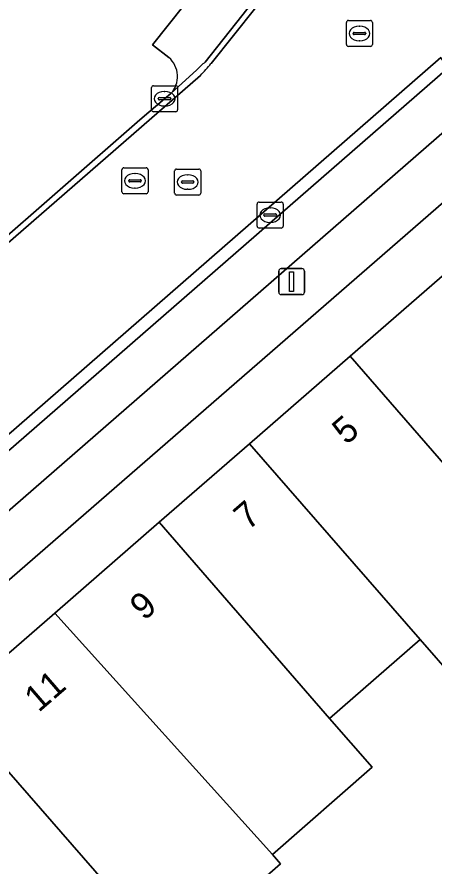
# Model space of a CAD drawing. Extents: x 161881 to 162523, y 381678 to 382381.
# Drawn here: x 162073.2 to 162089.24, y 382104.65 to 382137.32 of the extents above; entities that cross this region are included whole.
import ezdxf

# ---------------------------------------------------------------- set-up
doc = ezdxf.new("R2010")
doc.units = 0
for name, color, linetype in [('IMGEO_Erf', 7, 'Continuous'), ('IMGEO_Kolk', 7, 'Continuous'), ('IMGEO_Lichtmast', 7, 'Continuous'), ('IMGEO_Pand', 7, 'Continuous'), ('IMGEO_Pand_nummerreeks', 7, 'Continuous'), ('IMGEO_Parkeervlak_open', 7, 'Continuous'), ('IMGEO_Rijbaan_lokaal_open', 7, 'Continuous'), ('IMGEO_Rioolput', 7, 'Continuous'), ('IMGEO_Voetpad_open', 7, 'Continuous')]:
    doc.layers.add(name, color=color, linetype=linetype)

msp = doc.modelspace()

# ---------------------------------------------------------------- linework, layer by layer
at = {"layer": 'IMGEO_Erf'}
for points in [[(162094.812, 382134.731), (162045.016, 382091.412), (162046.474, 382089.736), (162054.365, 382081.454)], [(162054.137, 382083.272), (162047.556, 382090.818), (162051.36, 382094.127), (162055.4, 382097.641), (162059.405, 382101.124), (162062.911, 382104.174), (162066.755, 382107.518), (162070.6, 382110.862), (162074.647, 382114.382), (162078.667, 382117.878), (162082.144, 382120.902), (162086.012, 382124.267), (162090.338, 382128.029)], [(162090.02, 382111.857), (162088.706, 382113.366), (162085.22, 382110.331), (162086.856, 382108.447), (162083.028, 382105.097), (162083.336, 382104.728), (162079.152, 382101.078), (162078.812, 382101.467), (162074.973, 382098.113), (162071.133, 382094.758), (162070.479, 382095.507), (162066.981, 382092.451), (162067.968, 382091.321), (162063.941, 382087.819), (162059.914, 382084.317)]]:
    msp.add_lwpolyline(points, dxfattribs=at)
at = {"layer": 'IMGEO_Kolk'}
for p, q in [((162078.373, 382133.752), (162078.373, 382134.604)), ((162078.448, 382134.678), (162079.3, 382134.678)), ((162078.861, 382134.458), (162078.886, 382134.458)), ((162079.374, 382134.604), (162079.374, 382133.752)), ((162078.632, 382134.172), (162078.632, 382134.184)), ((162079.07, 382134.135), (162078.672, 382134.135)), ((162078.675, 382134.221), (162079.073, 382134.221)), ((162079.116, 382134.184), (162079.116, 382134.172)), ((162078.884, 382133.898), (162078.859, 382133.898)), ((162079.3, 382133.678), (162078.448, 382133.678)), ((162082.509, 382130.2), (162083.361, 382130.2)), ((162082.434, 382129.274), (162082.434, 382130.126)), ((162082.922, 382129.98), (162082.947, 382129.98)), ((162083.435, 382130.126), (162083.435, 382129.274)), ((162082.693, 382129.694), (162082.693, 382129.706)), ((162083.131, 382129.657), (162082.733, 382129.657)), ((162082.736, 382129.743), (162083.134, 382129.743)), ((162083.177, 382129.706), (162083.177, 382129.694)), ((162083.361, 382129.2), (162082.509, 382129.2)), ((162082.945, 382129.42), (162082.92, 382129.42))]:
    msp.add_line(p, q, dxfattribs=at)
for points in [[(162078.373, 382133.752), (162078.373, 382134.604)], [(162078.448, 382134.678), (162079.3, 382134.678)], [(162079.374, 382134.604), (162079.374, 382133.752)], [(162079.3, 382133.678), (162078.448, 382133.678)], [(162082.509, 382130.2), (162083.361, 382130.2)], [(162082.434, 382129.274), (162082.434, 382130.126)], [(162083.435, 382130.126), (162083.435, 382129.274)], [(162083.361, 382129.2), (162082.509, 382129.2)]]:
    msp.add_lwpolyline(points, dxfattribs=at)
for centre, radius, start, end in [((162078.45, 382134.602), 0.0765, 91.552, 178.448), ((162078.45, 382134.602), 0.0765, 91.552, 178.448), ((162079.298, 382134.602), 0.0765, 1.552, 88.448), ((162079.298, 382134.602), 0.0765, 1.552, 88.448), ((162078.672, 382134.181), 0.0403, 85.8775, 175.7526), ((162078.669, 382134.171), 0.0366, 178.938, 274.7102), ((162079.073, 382134.178), 0.043, 264.8664, 352.4533), ((162079.077, 382134.183), 0.0386, 1.7309, 96.639), ((162078.45, 382133.754), 0.0765, 181.552, 268.448), ((162078.45, 382133.754), 0.0765, 181.552, 268.448), ((162079.298, 382133.754), 0.0765, 271.552, 358.448), ((162079.298, 382133.754), 0.0765, 271.552, 358.448), ((162082.511, 382130.124), 0.0765, 91.552, 178.448), ((162082.511, 382130.124), 0.0765, 91.552, 178.448), ((162083.359, 382130.124), 0.0765, 1.552, 88.448), ((162083.359, 382130.124), 0.0765, 1.552, 88.448), ((162082.733, 382129.703), 0.0403, 85.8775, 175.7526), ((162082.73, 382129.693), 0.0366, 178.938, 274.7102), ((162083.134, 382129.7), 0.043, 264.8664, 352.4533), ((162083.138, 382129.705), 0.0386, 1.7309, 96.639), ((162082.511, 382129.276), 0.0765, 181.552, 268.448), ((162082.511, 382129.276), 0.0765, 181.552, 268.448), ((162083.359, 382129.276), 0.0765, 271.552, 358.448), ((162083.359, 382129.276), 0.0765, 271.552, 358.448)]:
    msp.add_arc(centre, radius, start, end, dxfattribs=at)
for centre, major_axis, ratio, start_param, end_param in [((162078.86, 382134.178), (-0.387, 0.002), 0.722429, 4.712389, 7.853982), ((162078.885, 382134.178), (-0.39, 0.002), 0.717154, 1.570796, 4.712389), ((162082.921, 382129.7), (-0.387, 0.002), 0.722429, 4.712389, 7.853982), ((162082.946, 382129.7), (-0.39, 0.002), 0.717154, 1.570796, 4.712389)]:
    msp.add_ellipse(centre, major_axis=major_axis, ratio=ratio, start_param=start_param, end_param=end_param, dxfattribs=at)
at = {"layer": 'IMGEO_Lichtmast'}
for p, q in [((162083.263, 382126.739), (162083.263, 382127.539)), ((162083.263, 382127.539), (162083.263, 382126.739)), ((162083.363, 382127.639), (162084.153, 382127.639)), ((162084.153, 382127.639), (162083.363, 382127.639)), ((162084.253, 382127.539), (162084.253, 382126.739)), ((162084.253, 382126.739), (162084.253, 382127.539)), ((162084.153, 382126.639), (162083.363, 382126.639)), ((162083.363, 382126.639), (162084.153, 382126.639))]:
    msp.add_line(p, q, dxfattribs=at)
msp.add_lwpolyline([(162083.683, 382127.514), (162083.833, 382127.514), (162083.833, 382126.764), (162083.683, 382126.764), (162083.683, 382127.514)], dxfattribs=at)
for centre, start, end in [((162083.363, 382127.539), 90, 180), ((162083.363, 382127.539), 90, 180), ((162084.153, 382127.539), 0, 90), ((162084.153, 382127.539), 360, 90), ((162083.363, 382126.739), 180, 270), ((162083.363, 382126.739), 180, 270), ((162084.153, 382126.739), 270, 0), ((162084.153, 382126.739), 270, 0)]:
    msp.add_arc(centre, 0.1, start, end, dxfattribs=at)
at = {"layer": 'IMGEO_Pand'}
for points in [[(162090.338, 382128.029), (162086.012, 382124.267), (162093.878, 382115.216), (162094.336, 382114.689), (162098.524, 382118.336), (162097.758, 382119.243)], [(162086.012, 382124.267), (162082.144, 382120.902), (162088.706, 382113.366), (162090.02, 382111.857), (162093.878, 382115.216)], [(162082.144, 382120.902), (162078.667, 382117.878), (162085.22, 382110.331), (162088.706, 382113.366)], [(162078.667, 382117.878), (162074.647, 382114.382), (162083.028, 382105.097), (162086.856, 382108.447), (162085.22, 382110.331)], [(162074.647, 382114.382), (162070.6, 382110.862), (162078.812, 382101.467), (162079.152, 382101.078), (162083.336, 382104.728), (162083.028, 382105.097)], [(162070.6, 382110.862), (162066.755, 382107.518), (162074.973, 382098.113), (162078.812, 382101.467)]]:
    msp.add_lwpolyline(points, close=True, dxfattribs=at)
at = {"layer": 'IMGEO_Parkeervlak_open'}
for points in [[(162089.765, 382135.352), (162060.132, 382109.524)], [(162060.865, 382109.155), (162061.499, 382108.414), (162090.927, 382134.045), (162090.608, 382134.346), (162090.308, 382134.665)]]:
    msp.add_lwpolyline(points, dxfattribs=at)
at = {"layer": 'IMGEO_Rijbaan_lokaal_open'}
for points in [[(162085.814, 382142.015), (162085.823, 382142.026), (162085.631, 382142.179), (162084.661, 382140.952), (162080.432, 382135.586)], [(162089.787, 382138.04), (162090.245, 382138.622), (162090.363, 382138.772), (162085.823, 382142.026), (162085.814, 382142.015), (162080.659, 382135.532)], [(162080.659, 382135.532), (162085.814, 382142.015)], [(162080.253, 382135.078), (162068.499, 382124.843), (162062.239, 382119.267), (162037.797, 382098.117), (162037.509, 382098.473), (162034.321, 382102.015), (162033.172, 382100.991), (162033.004, 382100.842), (162039.632, 382091.47), (162041.229, 382092.869), (162042.236, 382091.698), (162043.757, 382093.013), (162042.637, 382094.281), (162042.331, 382094.626), (162089.5, 382135.76)], [(162089.765, 382135.352), (162089.5, 382135.76), (162042.331, 382094.626), (162042.637, 382094.281), (162057.277, 382107.051)], [(162052.937, 382111.975), (162037.509, 382098.473), (162037.797, 382098.117), (162062.239, 382119.267), (162068.499, 382124.843), (162080.253, 382135.078)], [(162080.118, 382135.286), (162079.109, 382134.375), (162078.874, 382134.178), (162077.927, 382133.363), (162066.058, 382123), (162063.942, 382121.182), (162055.435, 382113.796), (162054.076, 382112.578), (162053.665, 382112.21)], [(162060.132, 382109.524), (162089.765, 382135.352)]]:
    msp.add_lwpolyline(points, dxfattribs=at)
for centre, radius, start, end in [((162082.299, 382133.318), 2.937, 129.4546, 137.933), ((162074.218, 382140.883), 8.373, 316.1104, 320.2788), ((162074.218, 382140.883), 8.373, 316.1104, 320.2788)]:
    msp.add_arc(centre, radius, start, end, dxfattribs=at)
at = {"layer": 'IMGEO_Rioolput'}
for p, q in [((162085.868, 382136.263), (162085.868, 382137.115)), ((162085.943, 382137.189), (162086.795, 382137.189)), ((162086.869, 382137.115), (162086.869, 382136.263)), ((162086.127, 382136.683), (162086.127, 382136.695)), ((162086.17, 382136.732), (162086.568, 382136.732)), ((162086.356, 382136.969), (162086.381, 382136.969)), ((162086.611, 382136.695), (162086.611, 382136.683)), ((162086.565, 382136.646), (162086.167, 382136.646)), ((162086.379, 382136.409), (162086.354, 382136.409)), ((162086.795, 382136.189), (162085.943, 382136.189)), ((162077.235, 382130.593), (162077.235, 382131.445)), ((162077.31, 382131.519), (162078.162, 382131.519)), ((162078.236, 382131.445), (162078.236, 382130.593)), ((162079.336, 382131.472), (162080.188, 382131.472)), ((162077.723, 382131.299), (162077.748, 382131.299)), ((162079.261, 382130.546), (162079.261, 382131.398)), ((162079.749, 382131.252), (162079.774, 382131.252)), ((162080.262, 382131.398), (162080.262, 382130.546)), ((162077.494, 382131.013), (162077.494, 382131.025)), ((162077.932, 382130.976), (162077.534, 382130.976)), ((162077.537, 382131.062), (162077.935, 382131.062)), ((162077.978, 382131.025), (162077.978, 382131.013)), ((162079.52, 382130.966), (162079.52, 382130.978)), ((162079.958, 382130.929), (162079.56, 382130.929)), ((162079.563, 382131.015), (162079.961, 382131.015)), ((162080.004, 382130.978), (162080.004, 382130.966)), ((162078.162, 382130.519), (162077.31, 382130.519)), ((162077.746, 382130.739), (162077.721, 382130.739)), ((162080.188, 382130.472), (162079.336, 382130.472)), ((162079.772, 382130.692), (162079.747, 382130.692))]:
    msp.add_line(p, q, dxfattribs=at)
for points in [[(162085.868, 382136.263), (162085.868, 382137.115)], [(162085.943, 382137.189), (162086.795, 382137.189)], [(162086.869, 382137.115), (162086.869, 382136.263)], [(162086.795, 382136.189), (162085.943, 382136.189)], [(162077.235, 382130.593), (162077.235, 382131.445)], [(162077.31, 382131.519), (162078.162, 382131.519)], [(162078.236, 382131.445), (162078.236, 382130.593)], [(162079.336, 382131.472), (162080.188, 382131.472)], [(162079.261, 382130.546), (162079.261, 382131.398)], [(162080.262, 382131.398), (162080.262, 382130.546)], [(162078.162, 382130.519), (162077.31, 382130.519)], [(162080.188, 382130.472), (162079.336, 382130.472)]]:
    msp.add_lwpolyline(points, dxfattribs=at)
for centre, radius, start, end in [((162085.945, 382137.113), 0.0765, 91.552, 178.448), ((162085.945, 382137.113), 0.0765, 91.552, 178.448), ((162086.793, 382137.113), 0.0765, 1.552, 88.448), ((162086.793, 382137.113), 0.0765, 1.552, 88.448), ((162086.167, 382136.692), 0.0403, 85.8775, 175.7526), ((162086.164, 382136.682), 0.0366, 178.938, 274.7102), ((162086.568, 382136.689), 0.043, 264.8664, 352.4533), ((162086.572, 382136.694), 0.0386, 1.7309, 96.639), ((162085.945, 382136.265), 0.0765, 181.552, 268.448), ((162085.945, 382136.265), 0.0765, 181.552, 268.448), ((162086.793, 382136.265), 0.0765, 271.552, 358.448), ((162086.793, 382136.265), 0.0765, 271.552, 358.448), ((162077.312, 382131.443), 0.0765, 91.552, 178.448), ((162077.312, 382131.443), 0.0765, 91.552, 178.448), ((162078.16, 382131.443), 0.0765, 1.552, 88.448), ((162078.16, 382131.443), 0.0765, 1.552, 88.448), ((162079.338, 382131.396), 0.0765, 91.552, 178.448), ((162079.338, 382131.396), 0.0765, 91.552, 178.448), ((162080.186, 382131.396), 0.0765, 1.552, 88.448), ((162080.186, 382131.396), 0.0765, 1.552, 88.448), ((162077.534, 382131.022), 0.0403, 85.8775, 175.7526), ((162077.531, 382131.012), 0.0366, 178.938, 274.7102), ((162077.935, 382131.019), 0.043, 264.8664, 352.4533), ((162077.939, 382131.024), 0.0386, 1.7309, 96.639), ((162079.56, 382130.975), 0.0403, 85.8775, 175.7526), ((162079.557, 382130.965), 0.0366, 178.938, 274.7102), ((162079.961, 382130.972), 0.043, 264.8664, 352.4533), ((162079.965, 382130.977), 0.0386, 1.7309, 96.639), ((162077.312, 382130.595), 0.0765, 181.552, 268.448), ((162077.312, 382130.595), 0.0765, 181.552, 268.448), ((162078.16, 382130.595), 0.0765, 271.552, 358.448), ((162078.16, 382130.595), 0.0765, 271.552, 358.448), ((162079.338, 382130.548), 0.0765, 181.552, 268.448), ((162079.338, 382130.548), 0.0765, 181.552, 268.448), ((162080.186, 382130.548), 0.0765, 271.552, 358.448), ((162080.186, 382130.548), 0.0765, 271.552, 358.448)]:
    msp.add_arc(centre, radius, start, end, dxfattribs=at)
for centre, major_axis, ratio, start_param, end_param in [((162086.355, 382136.689), (-0.387, 0.002), 0.722429, 4.712389, 7.853982), ((162086.38, 382136.689), (-0.39, 0.002), 0.717154, 1.570796, 4.712389), ((162077.722, 382131.019), (-0.387, 0.002), 0.722429, 4.712389, 7.853982), ((162077.747, 382131.019), (-0.39, 0.002), 0.717154, 1.570796, 4.712389), ((162079.748, 382130.972), (-0.387, 0.002), 0.722429, 4.712389, 7.853982), ((162079.773, 382130.972), (-0.39, 0.002), 0.717154, 1.570796, 4.712389)]:
    msp.add_ellipse(centre, major_axis=major_axis, ratio=ratio, start_param=start_param, end_param=end_param, dxfattribs=at)
at = {"layer": 'IMGEO_Voetpad_open'}
for points in [[(162046.652, 382148.942), (162046.944, 382148.616), (162051.211, 382143.73), (162051.478, 382143.425), (162053.879, 382145.512), (162065.711, 382135.244), (162059.846, 382130.148), (162066.058, 382123), (162077.927, 382133.363), (162078.874, 382134.178), (162079.109, 382134.375)], [(162083.289, 382140.811), (162082.53, 382141.435), (162078.414, 382136.257), (162079.037, 382135.765)], [(162079.037, 382135.765), (162078.414, 382136.257), (162082.53, 382141.435), (162083.289, 382140.811)], [(162080.432, 382135.586), (162084.661, 382140.952)], [(162079.109, 382134.375), (162080.118, 382135.286)], [(162090.308, 382134.665), (162090.608, 382134.346), (162090.927, 382134.045), (162061.499, 382108.414), (162061.496, 382108.207), (162060.797, 382107.623), (162059.375, 382109.235), (162057.984, 382108.023), (162059.407, 382106.418), (162058.417, 382105.55), (162058.2, 382105.55), (162043.757, 382093.013), (162042.236, 382091.698), (162042.306, 382091.549), (162043.519, 382090.148), (162045.016, 382091.412), (162094.812, 382134.731)]]:
    msp.add_lwpolyline(points, dxfattribs=at)
for centre, radius, start, end in [((162078.412, 382135.036), 0.96, 316.5093, 49.4211), ((162078.412, 382135.036), 0.96, 316.5093, 49.4211), ((162082.299, 382133.318), 2.937, 129.4546, 137.933)]:
    msp.add_arc(centre, radius, start, end, dxfattribs=at)

# ---------------------------------------------------------------- texts
at = {"layer": 'IMGEO_Pand_nummerreeks'}
for s, p in [('5', (162085.866, 382120.828)), ('7', (162082.084, 382117.539)), ('9', (162078.086, 382114.061)), ('11', (162074.027, 382110.534))]:
    msp.add_text(s, height=1, rotation=40.8175, dxfattribs=at).set_placement(p)

doc.saveas('drawing.dxf')
